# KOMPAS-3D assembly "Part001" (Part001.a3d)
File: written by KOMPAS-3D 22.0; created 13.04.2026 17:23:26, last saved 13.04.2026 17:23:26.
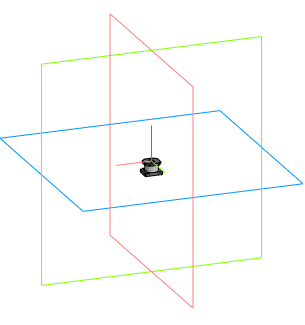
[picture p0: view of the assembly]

Document properties: Автор: Andrey; Полное имя файла: C:\Users\User1\Documents\Part001.a3d

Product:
- Part/product: Part001

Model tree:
1. Операция без истории:1
2. Операция без истории:2
3. Операция без истории:3
4. Операция без истории:4
5. Операция без истории:5
6. Операция без истории:6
